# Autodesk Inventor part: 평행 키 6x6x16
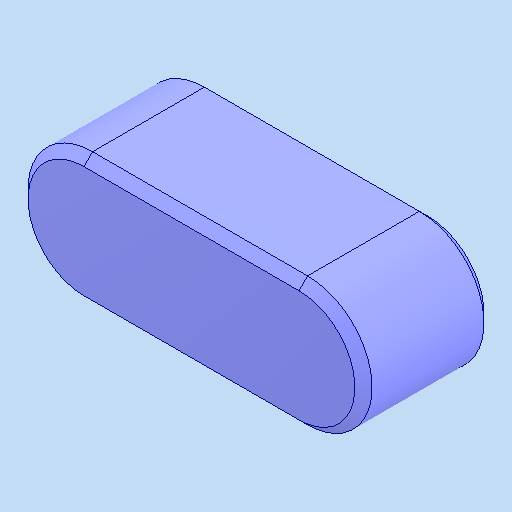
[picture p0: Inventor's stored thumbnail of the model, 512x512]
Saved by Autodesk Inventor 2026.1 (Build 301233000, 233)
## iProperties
Created: 2025-11
Part Number: 평행 키 6x6x16
Material: 강철, 연강
Description: 키 및 해당 키홈
Document SubType Name: Modeling
Designer: PC-30
Density: 7.85 g/cm^3
Appearance: 기본값
Author: jhkim
Sending System: Autodesk Inventor 2026
Preprocessor: ST-DEVELOPER v20.1
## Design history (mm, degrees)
feature "Solid1"
node "솔리드1"
